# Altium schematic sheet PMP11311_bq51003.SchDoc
size 431 x 279 mm; Date: Not shown in title block; ApprovedBy: Not shown in title block; CheckedBy: Not shown in title block; Author: Not shown in title block; CompanyName: Not shown in title block; Engineer: Not shown in title block; Organization: Not shown in title block; Address1: Not shown in title block; Address2: Not shown in title block; Address3: Not shown in title block; Address4: Not shown in title block; DocumentNumber: 1; Revision: Use project parameter SCH_Rev; SheetNumber: 2; SheetTotal: 3; PageSetup: Record=PageOptions¦CenterHorizontal=True¦CenterVertical=True¦PrintScale=1.00¦XCorrection=1.00¦YCorrection=1.00¦PrintKind=0¦BorderSize=5000000¦LeftOffset=0¦BottomOffset=0¦Orientation=2¦PaperLength=1000¦PaperWidth=1000¦Scale=100¦PaperSource=15¦PrintQuality=600¦MediaType=1¦DitherType=10¦PaperKind=Letter¦PrintScaleMode=1
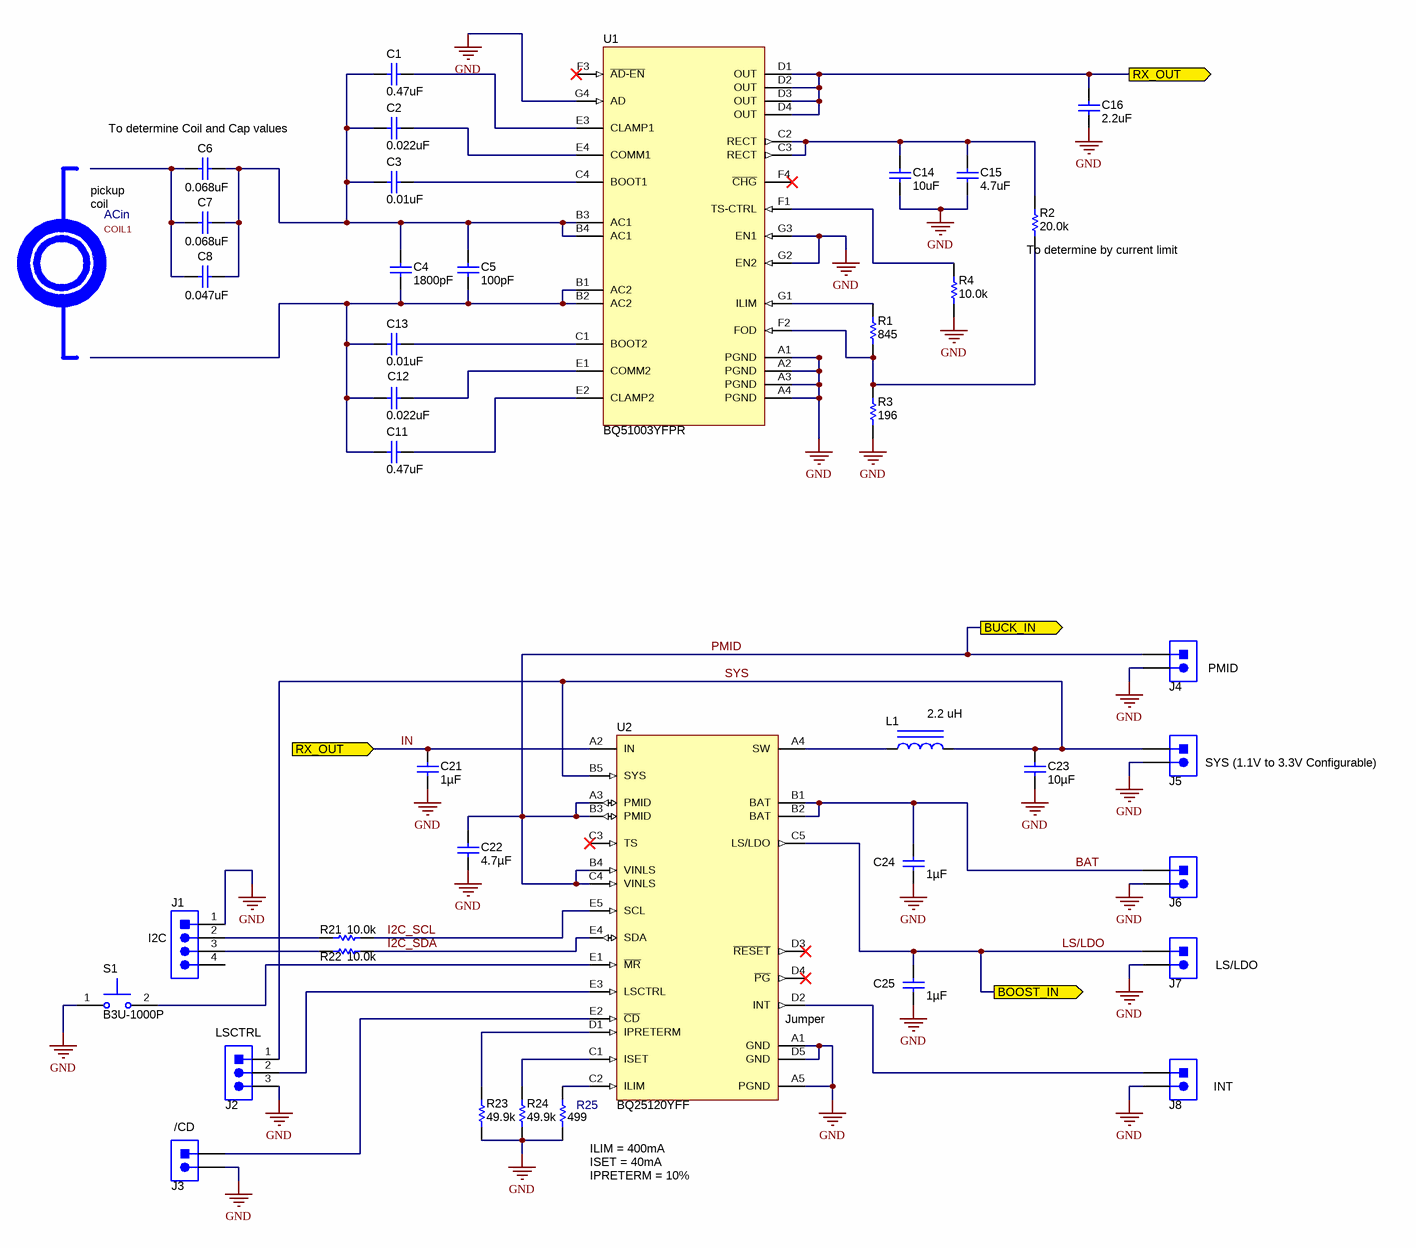
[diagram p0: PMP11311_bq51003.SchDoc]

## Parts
C1  ValueDisplayed: 0.47uF  [0603L]  (hidden comment: GRM188R71E474KA12D)
C2  ValueDisplayed: 0.022uF  [0402L]  (hidden comment: GRM155R71E223KA61D)
C3  ValueDisplayed: 0.01uF  [0402L]  (hidden comment: GRM155R71E103KA01D)
C4  ValueDisplayed: 1800pF  [0402]  (hidden comment: GRM155R71H182KA01D)
C5  ValueDisplayed: 100pF  [0201L]  (hidden comment: GRM033R71E101KA01D)
C6  ValueDisplayed: 0.068uF  [0603L]  (hidden comment: GRM188R71E683KA01D)
C7  ValueDisplayed: 0.068uF  [0603L]  (hidden comment: GRM188R71E683KA01D)
C8  ValueDisplayed: 0.047uF  [0603L]  (hidden comment: 06033C473JAT2A)
C11  ValueDisplayed: 0.47uF  [0603L]  (hidden comment: GRM188R71E474KA12D)
C12  ValueDisplayed: 0.022uF  [0402L]  (hidden comment: GRM155R71E223KA61D)
C13  ValueDisplayed: 0.01uF  [0402L]  (hidden comment: GRM155R71E103KA01D)
C14  ValueDisplayed: 10uF  [0603L]  (hidden comment: EMK107BBJ106MA-T)
C15  ValueDisplayed: 4.7uF  [0402L]  (hidden comment: GRM188R61C475KAAJ)
C16  ValueDisplayed: 2.2uF  [0402L]  (hidden comment: C1005X5R1A225K050BC)
C21  ValueDisplayed: 1µF  [0402]  (hidden comment: C1005X5R1E105K050BC)
C22  ValueDisplayed: 4.7µF  [0402]  (hidden comment: GRM155R61C475ME11D)
C23  ValueDisplayed: 10µF  [0402]  (hidden comment: CL05A106MP5NUNC)
C24  ValueDisplayed: 1µF  [0402]  (hidden comment: GRM155R61A105KE15D)
C25  ValueDisplayed: 1µF  [0402]  (hidden comment: GRM155R61A105KE15D)
J1  (no value)  [CONN_22-05-3041]
J2  PEC03SAAN  [CONN_PEC03SAAN]  (value not drawn)
J3  PEC02SAAN  [CONN_PEC02SAAN]  (value not drawn)
J4  PEC02SAAN  [CONN_PEC02SAAN]  (value not drawn)
J5  PEC02SAAN  [CONN_PEC02SAAN]  (value not drawn)
J6  PEC02SAAN  [CONN_PEC02SAAN]  (value not drawn)
J7  PEC02SAAN  [CONN_PEC02SAAN]  (value not drawn)
J8  PEC02SAAN  [CONN_PEC02SAAN]  (value not drawn)
L1  value 2.2 uH  [2012]  (hidden comment: MDT2012-CXxRyM-R)
R1  ValueDisplayed: 845  [0201M]  (hidden comment: CRCW0201845RFKED)
R2  ValueDisplayed: 20.0k  [0201M]  (hidden comment: CRCW020120K0FKED)
R3  ValueDisplayed: 196  [0201M]  (hidden comment: CRCW0201196RFKED)
R4  ValueDisplayed: 10.0k  [0201M]  (hidden comment: MCR006YRTF1002)
R21  ValueDisplayed: 10.0k  [0402]  (hidden comment: ERJ-2RKF1002X)
R22  ValueDisplayed: 10.0k  [0402]  (hidden comment: ERJ-2RKF1002X)
R23  ValueDisplayed: 49.9k  [0402]  (hidden comment: CRCW040249K9FKED)
R24  ValueDisplayed: 49.9k  [0402]  (hidden comment: CRCW040249K9FKED)
R25  value 499  [0402]  (hidden comment: CRCW0402499RFKED)
S1  B3U-1000P  [SW_B3U-1000P]
U1  BQ51003YFPR  [YFP0028APAL]
U2  BQ25120YFF  [YFF0025AWAW]

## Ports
BOOST_IN (out), BUCK_IN (out), RX_OUT (in), RX_OUT (out)

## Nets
GND: C14.1 C15.2 C16.2 C21.2 C22.2 C23.2 C24.2 C25.2 J1.1 J2.3 J3.2 J4.2 J5.2 J6.2 J7.2 J8.2 R3.1 R4.1 R23.1 R24.1 R25.2 S1.1 U1.A1(PGND) U1.A2(PGND) U1.A3(PGND) U1.A4(PGND) U1.G2(EN2) U1.G3(EN1) U1.G4(AD) U2.A1(GND) U2.A5(PGND) U2.D5(GND)
BAT: C24.1 J6.1 U2.B1(BAT) U2.B2(BAT)
I2C_SCL: R21.2 U2.E5(SCL)
I2C_SDA: R22.2 U2.E4(SDA)
IN: C16.1 C21.1 U1.D1(OUT) U1.D2(OUT) U1.D3(OUT) U1.D4(OUT) U2.A2(IN) ; port RX_OUT
LS/LDO: C25.1 J7.1 U2.C5(LS/LDO) ; port BOOST_IN
PMID: C22.1 J4.1 U2.A3(PMID) U2.B3(PMID) U2.B4(VINLS) U2.C4(VINLS) ; port BUCK_IN
SYS: C23.1 J2.1 J5.1 L1.2 U2.B5(SYS)
NetC1_1: C1.1 U1.E3(CLAMP1)
NetC1_2: C1.2 C2.2 C3.2 C4.1 C5.2 C6.1 C7.1 C8.1 U1.B3(AC1) U1.B4(AC1)
NetC2_1: C2.1 U1.E4(COMM1)
NetC3_1: C3.1 U1.C4(BOOT1)
NetC4_2: C4.2 C5.1 C11.2 C12.2 C13.2 U1.B1(AC2) U1.B2(AC2)
NetC6_2: C6.2 C7.2 C8.2
NetC11_1: C11.1 U1.E2(CLAMP2)
NetC12_1: C12.1 U1.E1(COMM2)
NetC13_1: C13.1 U1.C1(BOOT2)
NetC14_2: C14.2 C15.1 R2.2 U1.C2(RECT) U1.C3(RECT)
NetJ1_2: J1.2 R21.1
NetJ1_3: J1.3 R22.1
NetJ2_2: J2.2 U2.E3(LSCTRL)
NetJ3_1: J3.1 U2.E2(~{CD})
NetJ8_1: J8.1 U2.D2(INT)
NetL1_1: L1.1 U2.A4(SW)
NetR1_1: R1.1 U1.G1(ILIM)
NetR1_2: R1.2 R2.1 R3.2 U1.F2(FOD)
NetR4_2: R4.2 U1.F1(TS-CTRL)
NetR23_2: R23.2 U2.D1(IPRETERM)
NetR24_2: R24.2 U2.C1(ISET)
NetR25_1: R25.1 U2.C2(ILIM)
NetS1_2: S1.2 U2.E1(~{MR})

Not connected (* = marked no-connect by the designer): J1 4; U1 F3(~{AD-EN})* F4(~{CHG})*; U2 C3(TS)* D3(~{RESET})* D4(~{PG})*

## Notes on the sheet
- (near C6) To determine Coil and Cap values
- pickup
  coil
- ACin
- (near R2) To determine by current limit
- (near J4) PMID
- (near J5) SYS (1.1V to 3.3V Configurable)
- (near J1) I2C
- (near J7) LS/LDO
- (near J2) LSCTRL
- (near U2) Jumper
- (near J8) INT
- (near J3) /CD
- (near R25) ILIM = 400mA
  ISET = 40mA
  IPRETERM = 10%
- Labels drawn without touching a wire or pin: COIL1

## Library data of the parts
C1 C11 = GRM188R71E474KA12D: CAP, CERM, 0.47uF, 25V, +/-10%, X7R, 0603; Manufacturer: MuRata; Polarized: N; CompType: Capacitor; U/M: EA; Cap_F: 0.00000047; Tolerance_%: 10; Value1: Unknown; VDC_V: 25; TaMin_C: -55; TaMax_C: 125; Cap_Case: 0603
C2 C12 = GRM155R71E223KA61D: CAP, CERM, 0.022uF, 25V, +/-10%, X7R, 0402; Manufacturer: MuRata; Polarized: N; CompType: Capacitor; U/M: EA; Cap_F: 0.000000022; Tolerance_%: 10; Value1: Unknown; VDC_V: 25; TaMin_C: -55; TaMax_C: 125; Cap_Case: 0402
C3 C13 = GRM155R71E103KA01D: CAP, CERM, 0.01uF, 25V, +/-10%, X7R, 0402; Manufacturer: MuRata; Polarized: N; CompType: Capacitor; U/M: EA; Cap_F: 0.00000001; Tolerance_%: 10; Value1: Unknown; VDC_V: 25; TaMin_C: -55; TaMax_C: 125; Cap_Case: 0402
C4 = GRM155R71H182KA01D: CAP, CERM, 1800 pF, 50 V, +/- 10%, X7R, 0402; Manufacturer: MuRata; Polarized: N; CompType: Capacitor; Value: 1800pF; U/M: EA; Cap_F: 0.0000000018; Tolerance_%: 10; Value1: Unknown; VDC_V: 50; Value2: 50V; TaMin_C: -55; TaMax_C: 125
C5 = GRM033R71E101KA01D: CAP, CERM, 100pF, 25V, +/-10%, X7R, 0201; Manufacturer: MuRata; Polarized: N; CompType: Capacitor; U/M: EA; Cap_F: 0.0000000001; Tolerance_%: 10; Value1: Unknown; VDC_V: 25; TaMin_C: -55; TaMax_C: 125; Cap_Case: 0201
C6 C7 = GRM188R71E683KA01D: CAP, CERM, 0.068uF, 25V, +/-10%, X7R, 0603; Manufacturer: MuRata; Polarized: N; CompType: Capacitor; U/M: EA; Cap_F: 0.000000068; Tolerance_%: 10; Value1: Unknown; VDC_V: 25; TaMin_C: -55; TaMax_C: 125; Cap_Case: 0603
C8 = 06033C473JAT2A: CAP, CERM, 0.047uF, 25V, +/-5%, X7R, 0603; Manufacturer: AVX; Polarized: N; CompType: Capacitor; U/M: EA; Cap_F: 0.000000047; Tolerance_%: 5; ESR_Ohm: 0.052; Value1: 0.052 ohm; VDC_V: 25; TaMin_C: -55; TaMax_C: 125; Cap_Case: 0603
C14 = EMK107BBJ106MA-T: CAP, CERM, 10uF, 16V, +/-20%, X5R, 0603; Manufacturer: Taiyo Yuden; Polarized: N; CompType: Capacitor; U/M: EA; Cap_F: 0.00001; Tolerance_%: 20; Value1: Unknown; VDC_V: 16; TaMin_C: -55; TaMax_C: 85; Cap_Case: 0603
C15 = GRM188R61C475KAAJ: CAP, CERM, 4.7uF, 16V, +/-10%, X5R, 0603; Manufacturer: MuRata; Polarized: N; CompType: Capacitor; U/M: EA; Cap_F: 0.0000047; Tolerance_%: 10; Value1: Unknown; VDC_V: 16; TaMin_C: -55; TaMax_C: 85; Cap_Case: 0603
C16 = C1005X5R1A225K050BC: CAP, CERM, 2.2uF, 10V, +/-10%, X5R, 0402; Manufacturer: TDK; Polarized: N; CompType: Capacitor; U/M: EA; Cap_F: 0.0000022; Tolerance_%: 10; Value1: Unknown; TaMin_C: -55; TaMax_C: 85; Cap_Case: 0402
C21 = C1005X5R1E105K050BC: CAP, CERM, 1 µF, 25 V, +/- 10%, X5R, 0402; Manufacturer: TDK; Polarized: N; CompType: Capacitor; Value: 1uF; U/M: EA; Cap_F: 0.000001; Tolerance_%: 10; Value1: Unknown; VDC_V: 25; Value2: 25V; TaMin_C: -55; TaMax_C: 80
C22 = GRM155R61C475ME11D: CAP, CERM, 4.7 µF, 16 V, +/- 20%, X5R, 0402; Manufacturer: MuRata; Polarized: N; CompType: Capacitor; Value: 4.7uF; U/M: EA; Cap_F: 0.0000047; Tolerance_%: 20; Value1: Unknown; VDC_V: 16; Value2: 16V; TaMin_C: -55; TaMax_C: 85
C23 = CL05A106MP5NUNC: CAP, CERM, 10 µF, 10 V, +/- 20%, X5R, 0402; Manufacturer: Samsung Electro-Mechanics; Polarized: N; CompType: Capacitor; Value: 10uF; U/M: EA; Cap_F: 0.00001; Tolerance_%: 20; Value1: Unknown; VDC_V: 10; Value2: 10V; TaMin_C: -55; TaMax_C: 85
C24 C25 = GRM155R61A105KE15D: CAP, CERM, 1 µF, 10 V, +/- 10%, X5R, 0402; Manufacturer: MuRata; Polarized: N; CompType: Capacitor; Value: 1uF; U/M: EA; Cap_F: 0.000001; Tolerance_%: 10; Value1: Unknown; Value2: 10V; TaMin_C: -55; TaMax_C: 85
J1 = 22-05-3041: Header (friction lock), 100mil, 4x1, R/A, TH; Manufacturer: Molex; SymbolCreator: a0412235; U/M: EA
J2 = PEC03SAAN: Header, 100mil, 3x1, Tin, TH; Manufacturer: Sullins Connector Solutions; SymbolCreator: a0799628; U/M: EA
J3-J8 = PEC02SAAN: Header, 100mil, 2x1, Tin plated, TH; Manufacturer: Sullins Connector Solutions; SymbolCreator: a0412235; U/M: EA
L1 = IND_MDT2012_SERIES: Inductor, SMT, 600mA, 245-milliohm, 2.2uH; Manufacturer: TOKO; PartNumber: MDT2012-CH2R2AN; Area: 11200
R1 = CRCW0201845RFKED: RES, 845, 1%, 0.05 W, 0201; Manufacturer: Vishay-Dale; CompType: Resistor; Value: 845; Value_Code: 845R; Tolerance_%: 1; Power_W: 0.05; Value2: 0.05W; VDC_V: 30; TempCo: 100 ppm/C; EIA_Code: E96; U/M: EA
R2 = CRCW020120K0FKED: RES, 20.0 k, 1%, 0.05 W, 0201; Manufacturer: Vishay-Dale; CompType: Resistor; Value: 20.0k; Res_ohm: 20000; Value_Code: 20k0; Tolerance_%: 1; Power_W: 0.05; Value2: 0.05W; VDC_V: 30; TempCo: 100 ppm/C; EIA_Code: E96; U/M: EA
R3 = CRCW0201196RFKED: RES, 196, 1%, 0.05 W, 0201; Manufacturer: Vishay-Dale; CompType: Resistor; Value: 196; Value_Code: 196R; Tolerance_%: 1; Power_W: 0.05; Value2: 0.05W; VDC_V: 30; TempCo: 100 ppm/C; EIA_Code: E96; U/M: EA
R4 = MCR006YRTF1002: RES, 10.0 k, 1%, 0.05 W, 0201; Manufacturer: Rohm; CompType: Resistor; Res_ohm: 10000; Value: 10.0k; Value_Code: 10k0; Tolerance_%: 1; Power_W: 0.05; Value2: 0.05W; VDC_V: 25; TempCo: 250 ppm/C; EIA_Code: E96; U/M: EA
R21 R22 = ERJ-2RKF1002X: RES, 10.0 k, 1%, 0.1 W, 0402; Manufacturer: Panasonic; CompType: Resistor; Value: 10.0k; Res_ohm: 10000; Value_Code: 10k0; Tolerance_%: 1; Power_W: 0.1; Value2: 0.1W; VDC_V: 50; TempCo: 100 ppm/C; EIA_Code: E96; U/M: EA
R23 R24 = CRCW040249K9FKED: RES, 49.9 k, 1%, 0.063 W, 0402; Manufacturer: Vishay-Dale; CompType: Resistor; Value: 49.9k; Res_ohm: 49900; Value_Code: 49k9; Tolerance_%: 1; Power_W: 0.063; Value2: 0.063W; VDC_V: 50; TempCo: 100 ppm/C; EIA_Code: E96; U/M: EA
R25 = CRCW0402499RFKED: RES, 499 ohm, 1%, 0.063W, 0402; Manufacturer: Vishay-Dale; CompType: Resistor; Value_Code: 499R; Tolerance_%: 1; Power_W: 0.063; VDC_V: 50; TempCo: 100 ppm/C; EIA_Code: E96; U/M: EA
S1 = B3U-1000P: SWITCH TACTILE SPST-NO 0.05A 12V; Manufacturer: Omron Electronic Components; SymbolCreator: a0412235; VDC_V: 12; SwitchFunction: Off-Mom; PositionCount: 1; CurrentRating_mA: 50
U1 = BQ51003YFPR: Highly Integrated Wireless Receiver Qi (WPC v1.1) Compliant Power Supply, YFP0028APAL; Alternate PartNumber: BQ51003YFPT; Manufacturer: Texas Instruments; SymbolCreator: Altium; CompType: IC; U/M: EA
U2 = BQ25120YFF: YFF0025AWAW; Manufacturer: Texas Instruments; Alternate Manufacturer: None; SymbolCreator: x0208326; CompType: IC; U/M: EA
